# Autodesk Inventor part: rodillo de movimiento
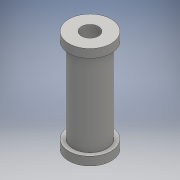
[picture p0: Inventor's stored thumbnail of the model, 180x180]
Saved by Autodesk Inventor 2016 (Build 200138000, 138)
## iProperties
Created: 2016-06
Part Number: rodillo de movimiento
Material: Genérico
Document SubType Name: Modeling
Designer: adm
Density: 1 g/cm^3
Appearance: Valor por defecto
Author: adm
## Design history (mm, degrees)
sketch "Boceto1"
  geometry: C1 r 12.5 at (0, 0); 1 further point
  constraints: 1 centre point, 1 coincident
  dimensions: "d0" = 25 diameter of C1
extrude "Extrusión1" new body sketch "Boceto1" distance "d1" = 5; taper "d2" = 0 deg
sketch "Boceto2"
  geometry: C1 r 10 at (0, 0); 1 further point
  constraints: 1 centre point, 1 coincident
  dimensions: "d3" = 20 diameter of C1
extrude "Extrusión2" join sketch "Boceto2" distance "d4" = 50; taper "d5" = 0 deg
sketch "Boceto3"
  geometry: C1 r 12.5 at (0, 0); 1 further point
  constraints: 1 centre point, 1 coincident
extrude "Extrusión3" join sketch "Boceto3" distance "d6" = 5; taper "d7" = 0 deg
hole "Agujero1" diameter "d10" = 10; stored, may be unused: countersink angle "d14" = 90 deg, drill point angle "d16" = 118 deg; dims "d8" = 10, "d9" = 10, "d11" = 6, "d12" = 4, "d13" = 2, "d15" = 70
sketch "Boceto4"
  geometry: L1 (12.5, 5)-(-12.5, 5) reference; C1 r 1.5 at (0, 10); C2 r 1.5 at (0, 50); 3 further points
  constraints: 2 centre point, 2 coincident
  dimensions: "d17" = 40 distance of point (0, 50) point (0, 10); "d18" = 5 distance from line of point (0, 10) L1; "d19" = 3 diameter of C1; "d20" = 3 diameter of C2
extrude "Extrusión4" cut sketch "Boceto4" distance "d21" = 12; taper "d22" = 0 deg
node "Sólido1"
